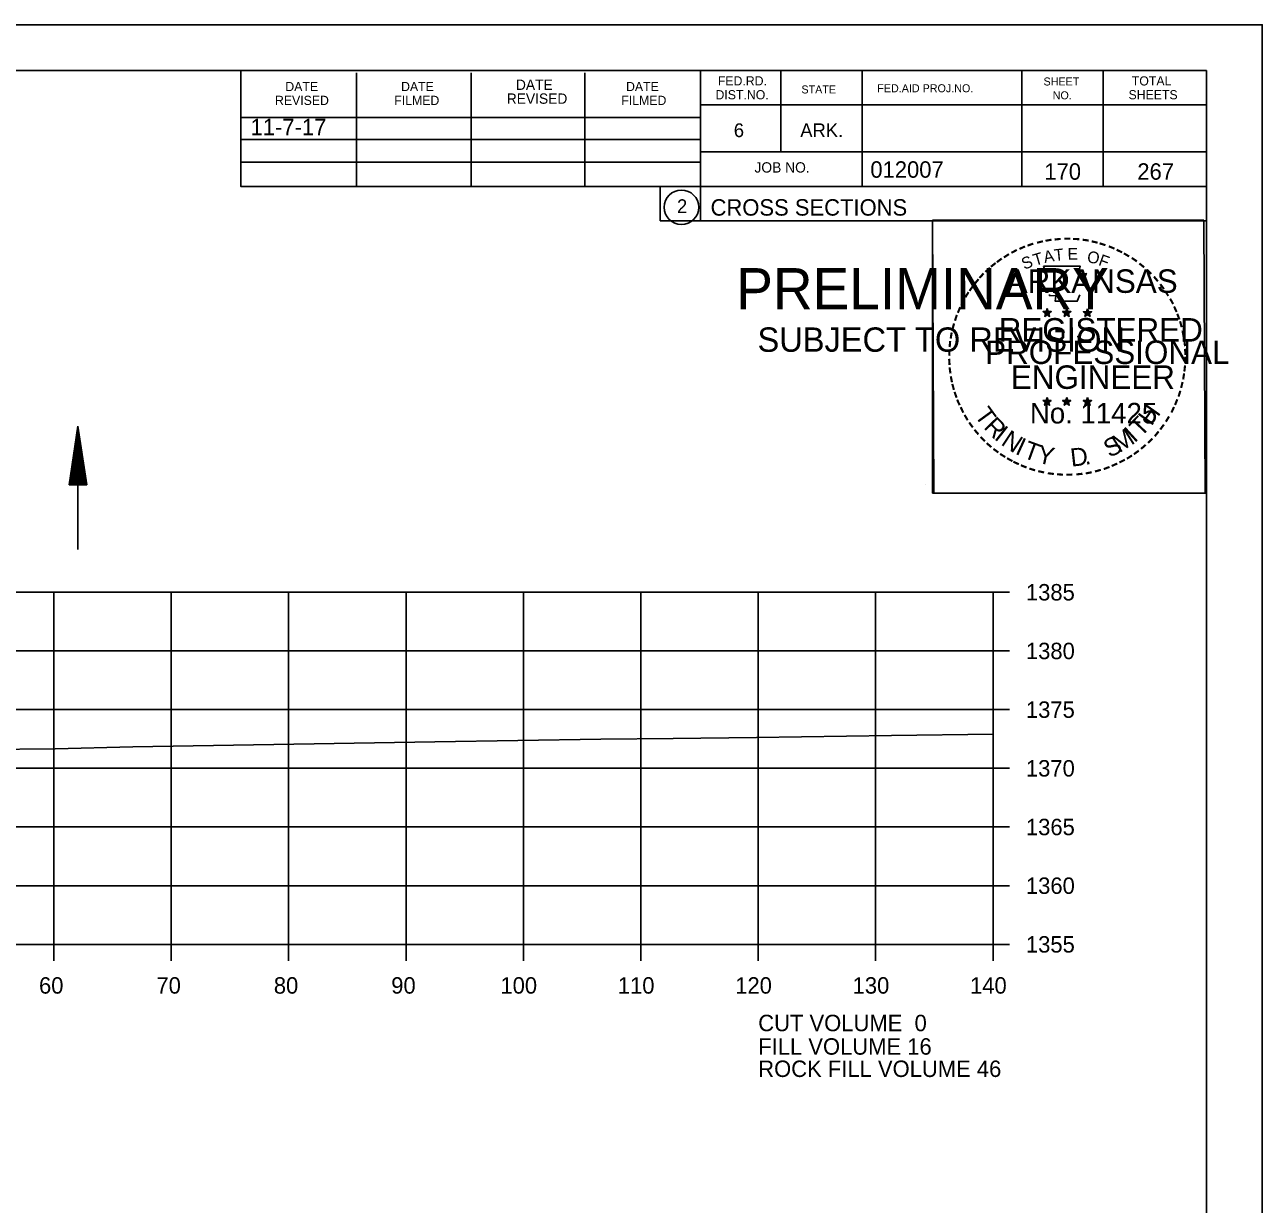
# Model space of a CAD drawing. Extents: x 1374311 to 1383814, y 384102 to 406278.
# Drawn here: x 1381686.2 to 1381791.6, y 388917.5 to 389018 of the extents above; entities that cross this region are included whole.
import ezdxf

# ---------------------------------------------------------------- set-up
doc = ezdxf.new("R2010")
doc.units = 0
for name, color, linetype in [('R_Axis', 7, 'Continuous'), ('R_Axis Annot', 7, 'Continuous'), ('R_Border', 7, 'Continuous'), ('R_Border PE', 7, 'Continuous'), ('R_Border Prem', 7, 'Continuous'), ('R_Draft', 7, 'Continuous'), ('R_Exist Surface', 7, 'Continuous'), ('R_Fin Surface', 7, 'Continuous'), ('R_Grid', 7, 'Continuous'), ('R_No Plot', 7, 'Continuous'), ('R_Water', 7, 'Continuous')]:
    doc.layers.add(name, color=color, linetype=linetype)

msp = doc.modelspace()

# ---------------------------------------------------------------- linework, layer by layer
at = {"layer": 'R_Axis'}
for p, q in [((1381768.66, 388939.68), (1381768.66, 388969.68)), ((1381770.06, 388969.68), (1381768.66, 388969.68)), ((1381770.06, 388964.68), (1381768.66, 388964.68)), ((1381770.06, 388959.68), (1381768.66, 388959.68)), ((1381770.06, 388954.68), (1381768.66, 388954.68)), ((1381770.06, 388949.68), (1381768.66, 388949.68)), ((1381770.06, 388944.68), (1381768.66, 388944.68)), ((1381488.66, 388939.68), (1381768.66, 388939.68)), ((1381688.66, 388938.28), (1381688.66, 388939.68)), ((1381698.66, 388938.28), (1381698.66, 388939.68)), ((1381708.66, 388938.28), (1381708.66, 388939.68)), ((1381718.66, 388938.28), (1381718.66, 388939.68)), ((1381728.66, 388938.28), (1381728.66, 388939.68)), ((1381738.66, 388938.28), (1381738.66, 388939.68)), ((1381748.66, 388938.28), (1381748.66, 388939.68)), ((1381758.66, 388938.28), (1381758.66, 388939.68)), ((1381768.66, 388938.28), (1381768.66, 388939.68)), ((1381770.06, 388939.68), (1381768.66, 388939.68))]:
    msp.add_line(p, q, dxfattribs=at)
at = {"layer": 'R_Border'}
for p, q in [((1381470.66, 389014.14), (1381786.84, 389014.14)), ((1381704.58, 389004.26), (1381704.58, 389014.14)), ((1381714.44, 389004.26), (1381714.44, 389013.94)), ((1381724.2, 389004.26), (1381724.2, 389013.94)), ((1381733.88, 389004.26), (1381733.88, 389013.94)), ((1381743.74, 389014.14), (1381743.74, 389001.34)), ((1381750.58, 389014.14), (1381750.58, 389007.2)), ((1381757.52, 389014.14), (1381757.52, 389004.26)), ((1381771.1, 389014.14), (1381771.1, 389004.26)), ((1381778.04, 389014.14), (1381778.04, 389004.26)), ((1381786.84, 388808.68), (1381786.84, 389014.14)), ((1381786.84, 389011.2), (1381743.74, 389011.2)), ((1381786.84, 389011.22), (1381786.84, 389011.22)), ((1381704.58, 389010.12), (1381743.74, 389010.12)), ((1381704.58, 389008.26), (1381743.74, 389008.26)), ((1381786.84, 389007.2), (1381743.74, 389007.2)), ((1381746.7, 389007.2), (1381786.84, 389007.2)), ((1381704.58, 389004.26), (1381704.58, 389006.32)), ((1381704.58, 389006.32), (1381743.74, 389006.32)), ((1381786.84, 389004.26), (1381704.58, 389004.26)), ((1381743.74, 389001.34), (1381786.84, 389001.34))]:
    msp.add_line(p, q, dxfattribs=at)
msp.add_circle((1381742.12, 389002.48), 1.47, dxfattribs=at)
at = {"layer": 'R_Border PE'}
for p, q in [((1381773.27, 388993.85), (1381773.23, 388993.6)), ((1381773.27, 388993.48), (1381773.27, 388993.85)), ((1381773.27, 388993.85), (1381773.32, 388993.6)), ((1381774.94, 388993.85), (1381774.9, 388993.6)), ((1381774.94, 388993.48), (1381774.94, 388993.85)), ((1381774.94, 388993.85), (1381774.99, 388993.6)), ((1381776.71, 388993.84), (1381776.66, 388993.59)), ((1381776.71, 388993.47), (1381776.71, 388993.84)), ((1381776.71, 388993.84), (1381776.75, 388993.59)), ((1381772.92, 388993.6), (1381773.27, 388993.48)), ((1381772.92, 388993.6), (1381773.18, 388993.55)), ((1381772.92, 388993.6), (1381773.16, 388993.47)), ((1381773.06, 388993.19), (1381773.27, 388993.48)), ((1381773.06, 388993.19), (1381773.18, 388993.43)), ((1381773.06, 388993.19), (1381773.27, 388993.4)), ((1381773.62, 388993.6), (1381773.27, 388993.48)), ((1381773.48, 388993.19), (1381773.27, 388993.48)), ((1381773.48, 388993.19), (1381773.27, 388993.4)), ((1381773.62, 388993.6), (1381773.33, 388993.55)), ((1381773.48, 388993.19), (1381773.35, 388993.48)), ((1381773.62, 388993.6), (1381773.41, 388993.49)), ((1381774.59, 388993.6), (1381774.94, 388993.48)), ((1381774.59, 388993.6), (1381774.85, 388993.55)), ((1381774.59, 388993.6), (1381774.83, 388993.47)), ((1381774.73, 388993.19), (1381774.94, 388993.48)), ((1381774.73, 388993.19), (1381774.85, 388993.43)), ((1381774.73, 388993.19), (1381774.94, 388993.4)), ((1381775.29, 388993.6), (1381774.94, 388993.48)), ((1381775.15, 388993.19), (1381774.94, 388993.48)), ((1381775.15, 388993.19), (1381774.94, 388993.4)), ((1381775.29, 388993.6), (1381775, 388993.55)), ((1381775.15, 388993.19), (1381775.02, 388993.48)), ((1381775.29, 388993.6), (1381775.08, 388993.49)), ((1381776.36, 388993.58), (1381776.71, 388993.47)), ((1381776.36, 388993.58), (1381776.61, 388993.54)), ((1381776.36, 388993.58), (1381776.59, 388993.46)), ((1381776.49, 388993.18), (1381776.71, 388993.47)), ((1381776.49, 388993.18), (1381776.62, 388993.42)), ((1381776.49, 388993.18), (1381776.7, 388993.39)), ((1381776.92, 388993.18), (1381776.7, 388993.39)), ((1381777.05, 388993.58), (1381776.71, 388993.47)), ((1381776.92, 388993.18), (1381776.71, 388993.47)), ((1381777.05, 388993.58), (1381776.77, 388993.53)), ((1381776.92, 388993.18), (1381776.78, 388993.47)), ((1381777.05, 388993.58), (1381776.85, 388993.48)), ((1381772.92, 388986.02), (1381773.27, 388985.91)), ((1381772.92, 388986.02), (1381773.17, 388985.98)), ((1381772.92, 388986.02), (1381773.16, 388985.9)), ((1381773.05, 388985.61), (1381773.27, 388985.91)), ((1381773.05, 388985.61), (1381773.18, 388985.86)), ((1381773.05, 388985.61), (1381773.27, 388985.83)), ((1381773.27, 388986.28), (1381773.23, 388986.02)), ((1381773.27, 388985.91), (1381773.27, 388986.28)), ((1381773.27, 388986.28), (1381773.32, 388986.03)), ((1381773.61, 388986.02), (1381773.27, 388985.91)), ((1381773.48, 388985.61), (1381773.27, 388985.91)), ((1381773.48, 388985.61), (1381773.27, 388985.83)), ((1381773.61, 388986.02), (1381773.33, 388985.97)), ((1381773.48, 388985.61), (1381773.34, 388985.91)), ((1381773.61, 388986.02), (1381773.41, 388985.92)), ((1381774.59, 388986.02), (1381774.94, 388985.91)), ((1381774.59, 388986.02), (1381774.84, 388985.98)), ((1381774.59, 388986.02), (1381774.82, 388985.9)), ((1381774.72, 388985.61), (1381774.94, 388985.91)), ((1381774.72, 388985.61), (1381774.85, 388985.86)), ((1381774.72, 388985.61), (1381774.93, 388985.83)), ((1381774.94, 388986.28), (1381774.9, 388986.02)), ((1381775.15, 388985.61), (1381774.93, 388985.83)), ((1381774.94, 388985.91), (1381774.94, 388986.28)), ((1381774.94, 388986.28), (1381774.99, 388986.03)), ((1381775.28, 388986.02), (1381774.94, 388985.91)), ((1381775.15, 388985.61), (1381774.94, 388985.91)), ((1381775.28, 388986.02), (1381775, 388985.97)), ((1381775.15, 388985.61), (1381775.01, 388985.91)), ((1381775.28, 388986.02), (1381775.08, 388985.92)), ((1381776.35, 388986.01), (1381776.7, 388985.9)), ((1381776.35, 388986.01), (1381776.61, 388985.97)), ((1381776.35, 388986.01), (1381776.59, 388985.89)), ((1381776.49, 388985.6), (1381776.7, 388985.9)), ((1381776.49, 388985.6), (1381776.61, 388985.85)), ((1381776.49, 388985.6), (1381776.7, 388985.82)), ((1381776.7, 388986.27), (1381776.66, 388986.01)), ((1381776.7, 388985.9), (1381776.7, 388986.27)), ((1381776.7, 388986.27), (1381776.75, 388986.02)), ((1381777.05, 388986.01), (1381776.7, 388985.9)), ((1381776.92, 388985.6), (1381776.7, 388985.9)), ((1381776.92, 388985.6), (1381776.7, 388985.82)), ((1381777.05, 388986.01), (1381776.76, 388985.96)), ((1381776.92, 388985.6), (1381776.78, 388985.9)), ((1381777.05, 388986.01), (1381776.85, 388985.91))]:
    msp.add_line(p, q, dxfattribs=at)
for points in [[(1381772.96, 388997.47), (1381773.23, 388996.65)], [(1381776.47, 388996.55), (1381776.62, 388996.84), (1381775.93, 388996.81), (1381776.08, 388997.47), (1381772.96, 388997.47)], [(1381773.46, 388995.05), (1381773.46, 388994.96), (1381774.02, 388994.94), (1381773.96, 388994.47), (1381775.83, 388994.47), (1381776.04, 388995.01)], [(1381773.27, 388993.85), (1381773.48, 388993.19), (1381772.92, 388993.6), (1381773.62, 388993.6), (1381773.06, 388993.19), (1381773.27, 388993.85)], [(1381774.94, 388993.85), (1381775.15, 388993.19), (1381774.59, 388993.6), (1381775.29, 388993.6), (1381774.73, 388993.19), (1381774.94, 388993.85)], [(1381776.71, 388993.84), (1381776.92, 388993.18), (1381776.36, 388993.58), (1381777.05, 388993.58), (1381776.49, 388993.18), (1381776.71, 388993.84)], [(1381773.27, 388986.28), (1381773.48, 388985.61), (1381772.92, 388986.02), (1381773.61, 388986.02), (1381773.05, 388985.61), (1381773.27, 388986.28)], [(1381774.94, 388986.28), (1381775.15, 388985.61), (1381774.59, 388986.02), (1381775.28, 388986.02), (1381774.72, 388985.61), (1381774.94, 388986.28)], [(1381776.7, 388986.27), (1381776.92, 388985.6), (1381776.35, 388986.01), (1381777.05, 388986.01), (1381776.49, 388985.6), (1381776.7, 388986.27)]]:
    msp.add_lwpolyline(points, dxfattribs=at)
for centre, radius in [((1381773.27, 388993.48), 0.172), ((1381773.27, 388993.48), 0.145), ((1381773.27, 388993.48), 0.116), ((1381773.27, 388993.48), 0.0991), ((1381773.27, 388993.48), 0.0747), ((1381773.27, 388993.48), 0.0495), ((1381773.27, 388993.48), 0.0296), ((1381774.94, 388993.48), 0.172), ((1381774.94, 388993.48), 0.145), ((1381774.94, 388993.48), 0.116), ((1381774.94, 388993.48), 0.0991), ((1381774.94, 388993.48), 0.0747), ((1381774.94, 388993.48), 0.0495), ((1381774.94, 388993.48), 0.0296), ((1381776.7, 388993.47), 0.172), ((1381776.7, 388993.47), 0.145), ((1381776.7, 388993.47), 0.116), ((1381776.7, 388993.47), 0.0991), ((1381776.7, 388993.47), 0.0747), ((1381776.7, 388993.47), 0.0495), ((1381776.7, 388993.47), 0.0296), ((1381773.27, 388985.91), 0.172), ((1381773.27, 388985.91), 0.145), ((1381773.27, 388985.91), 0.116), ((1381773.27, 388985.91), 0.0991), ((1381773.27, 388985.91), 0.0747), ((1381773.27, 388985.91), 0.0495), ((1381773.27, 388985.91), 0.0296), ((1381774.94, 388985.91), 0.172), ((1381774.94, 388985.91), 0.145), ((1381774.94, 388985.91), 0.116), ((1381774.94, 388985.91), 0.0991), ((1381774.94, 388985.91), 0.0747), ((1381774.94, 388985.91), 0.0495), ((1381774.94, 388985.91), 0.0296), ((1381776.7, 388985.9), 0.172), ((1381776.7, 388985.9), 0.145), ((1381776.7, 388985.9), 0.116), ((1381776.7, 388985.9), 0.0991), ((1381776.7, 388985.9), 0.0747), ((1381776.7, 388985.9), 0.0495), ((1381776.7, 388985.9), 0.0296)]:
    msp.add_circle(centre, radius, dxfattribs=at)
at = {"layer": 'R_Draft'}
for p, q in [((1381689.97, 388978.83), (1381690.72, 388983.83)), ((1381691.47, 388978.83), (1381690.72, 388983.83)), ((1381690.09, 388978.83), (1381690.72, 388983)), ((1381690.22, 388978.83), (1381690.72, 388982.14)), ((1381691.34, 388978.83), (1381690.72, 388983)), ((1381691.22, 388978.83), (1381690.72, 388982.14)), ((1381690.35, 388978.83), (1381690.72, 388981.31)), ((1381691.09, 388978.83), (1381690.72, 388981.31)), ((1381690.47, 388978.83), (1381690.72, 388980.46)), ((1381690.96, 388978.83), (1381690.72, 388980.46)), ((1381690.6, 388978.83), (1381690.72, 388979.62)), ((1381690.84, 388978.83), (1381690.72, 388979.62)), ((1381691.47, 388978.83), (1381689.97, 388978.83))]:
    msp.add_line(p, q, dxfattribs=at)
at = {"layer": 'R_Exist Surface'}
msp.add_lwpolyline([(1381567.33, 388953.99), (1381575.78, 388954.3), (1381586.09, 388955.07), (1381589.93, 388955.49), (1381596.86, 388955.76), (1381599.54, 388955.9), (1381601.13, 388955.76), (1381605.73, 388955.36), (1381615.89, 388955.54), (1381623.65, 388955.68), (1381646.48, 388956.09), (1381652.87, 388956.11), (1381674.54, 388956.12), (1381675.72, 388956.14), (1381682.71, 388956.27), (1381688.77, 388956.34), (1381695.4, 388956.5), (1381721.11, 388956.94), (1381735.25, 388957.15), (1381741.41, 388957.23), (1381748.5, 388957.31), (1381760.01, 388957.48), (1381768.66, 388957.59)], dxfattribs=at)
at = {"layer": 'R_Grid'}
for p, q in [((1381488.66, 388969.68), (1381768.66, 388969.68)), ((1381688.66, 388939.68), (1381688.66, 388969.68)), ((1381698.66, 388939.68), (1381698.66, 388969.68)), ((1381708.66, 388939.68), (1381708.66, 388969.68)), ((1381718.66, 388939.68), (1381718.66, 388969.68)), ((1381728.66, 388939.68), (1381728.66, 388969.68)), ((1381738.66, 388939.68), (1381738.66, 388969.68)), ((1381748.66, 388939.68), (1381748.66, 388969.68)), ((1381758.66, 388939.68), (1381758.66, 388969.68)), ((1381768.66, 388939.68), (1381768.66, 388969.68)), ((1381488.66, 388964.68), (1381768.66, 388964.68)), ((1381488.66, 388959.68), (1381768.66, 388959.68)), ((1381488.66, 388954.68), (1381768.66, 388954.68)), ((1381488.66, 388949.68), (1381768.66, 388949.68)), ((1381488.66, 388944.68), (1381768.66, 388944.68)), ((1381488.66, 388939.68), (1381768.66, 388939.68))]:
    msp.add_line(p, q, dxfattribs=at)
at = {"layer": 'R_No Plot'}
for p, q in [((1381458.26, 389018.04), (1381791.59, 389018.04)), ((1381762.87, 388978.88), (1381762.87, 388978.88))]:
    msp.add_line(p, q, dxfattribs=at)
for points in [[(1381458.25, 389018.04), (1381791.59, 389018.04), (1381791.59, 388804.7), (1381458.25, 388804.7)], [(1381704.58, 389014.14), (1381704.58, 389004.26), (1381740.31, 389004.26), (1381740.31, 389001.34), (1381763.51, 389001.34), (1381763.51, 388978.13), (1381786.84, 388978.13), (1381786.84, 388808.68), (1381470.66, 388808.68), (1381470.66, 389014.14)], [(1381763.51, 389001.37), (1381786.61, 389001.37), (1381786.72, 388978.13), (1381763.62, 388978.13)]]:
    msp.add_lwpolyline(points, close=True, dxfattribs=at)
at = {"layer": 'R_Water'}
msp.add_line((1381690.72, 388973.33), (1381690.72, 388983.83), dxfattribs=at)

# ---------------------------------------------------------------- texts
at = {"layer": 'R_Axis Annot'}
for s, p in [('1385', (1381771.46, 388968.98)), ('1380', (1381771.46, 388963.98)), ('1375', (1381771.46, 388958.98)), ('1370', (1381771.46, 388953.98)), ('1365', (1381771.46, 388948.98)), ('1360', (1381771.46, 388943.98)), ('1355', (1381771.46, 388938.98)), ('60', (1381687.4, 388935.48)), ('70', (1381697.4, 388935.48)), ('80', (1381707.4, 388935.48)), ('90', (1381717.4, 388935.48)), ('100', (1381726.7, 388935.48)), ('110', (1381736.7, 388935.48)), ('120', (1381746.7, 388935.48)), ('130', (1381756.7, 388935.48)), ('140', (1381766.7, 388935.48)), ('CUT VOLUME  0', (1381748.66, 388932.28)), ('FILL VOLUME 16', (1381748.66, 388930.28)), ('ROCK FILL VOLUME 46', (1381748.66, 388928.38))]:
    msp.add_text(s, height=1.4, dxfattribs=at).set_placement(p)
at = {"layer": 'R_Border'}
for s, height, p in [('DATE', 0.782, (1381708.38, 389012.38)), ('DATE', 0.782, (1381718.24, 389012.38)), ('DATE', 0.879, (1381728.02, 389012.48)), ('DATE', 0.782, (1381737.4, 389012.38)), ('FED.RD.', 0.782, (1381745.22, 389012.86)), ('STATE', 0.684, (1381752.34, 389012.18)), ('FED.AID PROJ.NO.', 0.684, (1381758.8, 389012.28)), ('SHEET', 0.684, (1381772.96, 389012.86)), ('TOTAL', 0.782, (1381780.48, 389012.86)), ('REVISED', 0.782, (1381707.5, 389011.2)), ('FILMED', 0.782, (1381717.66, 389011.2)), ('REVISED', 0.879, (1381727.24, 389011.3)), ('FILMED', 0.782, (1381737, 389011.2)), ('DIST.NO.', 0.782, (1381745.02, 389011.68)), ('NO.', 0.684, (1381773.74, 389011.68)), ('SHEETS', 0.782, (1381780.2, 389011.68)), ('6', 1.17, (1381746.58, 389008.46)), ('ARK.', 1.172, (1381752.24, 389008.46)), ('012007', 1.4, (1381758.21, 389005)), ('JOB NO.', 0.879, (1381748.34, 389005.44)), ('2', 1.17, (1381741.74, 389001.99)), ('CROSS SECTIONS', 1.4, (1381744.6, 389001.77))]:
    msp.add_text(s, height=height, rotation=360, dxfattribs=at).set_placement(p)
at = {"layer": 'R_Border PE'}
for s, height, rotation, p in [('-', 1.6, 24.3072, (1381771.08, 388998.33)), ('-', 1.6, 19.1761, (1381771.71, 388998.6)), ('-', 1.6, 13.6301, (1381772.46, 388998.84)), ('-', 1.6, 10.2193, (1381773.14, 388999)), ('-', 1.6, 5.8968, (1381773.87, 388999.11)), ('-', 1.6, 0.1862, (1381774.64, 388999.19)), ('E', 1, 0.8323, (1381775.01, 388998.01)), ('-', 1.6, 357.743, (1381775.36, 388999.17)), ('-', 1.6, 352.1617, (1381776.11, 388999.12)), ('-', 1.6, 347.2049, (1381776.83, 388999)), ('-', 1.6, 342.3362, (1381777.46, 388998.85)), ('-', 1.6, 337.8551, (1381778.2, 388998.62)), ('-', 1.6, 36.2317, (1381769.27, 388997.25)), ('-', 1.6, 34.0636, (1381769.85, 388997.64)), ('-', 1.6, 28.7918, (1381770.44, 388998.01)), ('S', 1, 21.594, (1381771.32, 388997.15)), ('T', 1, 16.4036, (1381772.23, 388997.48)), ('A', 1, 11.2132, (1381773.06, 388997.73)), ('T', 1, 6.0228, (1381773.91, 388997.9)), ('O', 1, 350.4515, (1381776.62, 388997.8)), ('F', 1, 340.0707, (1381777.57, 388997.57)), ('-', 1.6, 334.1211, (1381778.83, 388998.35)), ('-', 1.6, 329.6409, (1381779.41, 388998.07)), ('-', 1.6, 325.8627, (1381780.05, 388997.71)), ('-', 1.6, 48.423, (1381767.91, 388995.98)), ('-', 1.6, 42.9622, (1381768.36, 388996.45)), ('-', 1.6, 38.9507, (1381768.79, 388996.87)), ('ARKANSAS', 2, 360, (1381769.82, 388995.19)), ('-', 1.6, 320.5297, (1381780.66, 388997.28)), ('-', 1.6, 315.5786, (1381781.26, 388996.8)), ('-', 1.6, 54.2325, (1381767.1, 388994.92)), ('-', 1.6, 50.6142, (1381767.51, 388995.49)), ('-', 1.6, 309.8797, (1381781.83, 388996.25)), ('-', 1.6, 306.6522, (1381782.35, 388995.64)), ('-', 1.6, 58.0706, (1381766.77, 388994.4)), ('-', 1.4, 303.6753, (1381782.84, 388995.08)), ('-', 1.6, 67.7743, (1381766.2, 388993.17)), ('-', 1.6, 62.8713, (1381766.46, 388993.78)), ('-', 1.6, 299.6684, (1381783.16, 388994.47)), ('-', 1.6, 294.6628, (1381783.48, 388993.86)), ('-', 1.6, 72.3945, (1381765.98, 388992.54)), ('REGISTERED', 2, 360, (1381769.14, 388991.04)), ('DWB', 0.01, 360, (1381773.26, 388993.48)), ('DWB', 0.01, 360, (1381774.93, 388993.48)), ('DWB', 0.01, 360, (1381776.69, 388993.47)), ('-', 1.6, 290.5728, (1381783.74, 388993.28)), ('-', 1.6, 285.1233, (1381783.97, 388992.7)), ('-', 1.6, 81.2013, (1381765.65, 388991.11)), ('-', 1.6, 75.461, (1381765.78, 388991.83)), ('-', 1.6, 280.5493, (1381784.17, 388991.96)), ('-', 1.6, 85.1863, (1381765.57, 388990.42)), ('PROFESSIONAL', 2, 360, (1381767.99, 388989.13)), ('-', 1.6, 276.5962, (1381784.33, 388991.19)), ('-', 1.6, 94.1959, (1381765.58, 388989)), ('-', 1.6, 89.0622, (1381765.55, 388989.72)), ('-', 1.6, 274.3301, (1381784.39, 388990.47)), ('-', 1.6, 269.9407, (1381784.43, 388989.84)), ('-', 1.6, 98.9479, (1381765.66, 388988.33)), ('ENGINEER', 2, 360, (1381770.18, 388987.01)), ('-', 1.6, 263.5172, (1381784.41, 388989.17)), ('-', 1.6, 101.7149, (1381765.79, 388987.6)), ('-', 1.6, 105.4578, (1381765.95, 388987)), ('-', 1.6, 255.7626, (1381784.23, 388987.84)), ('-', 1.6, 260.9953, (1381784.34, 388988.52)), ('-', 1.6, 109.0874, (1381766.17, 388986.37)), ('-', 1.6, 252.8681, (1381784.05, 388987.12)), ('-', 1.6, 114.0643, (1381766.42, 388985.78)), ('-', 1.6, 115.7289, (1381766.73, 388985.16)), ('T', 1.54, 306.0406, (1381767.03, 388984.75)), ('No. 11425', 1.757, 360, (1381771.8, 388984.06)), ('DWB', 0.01, 360, (1381773.25, 388985.91)), ('DWB', 0.01, 360, (1381774.92, 388985.91)), ('DWB', 0.01, 360, (1381776.69, 388985.9)), ('H', 1.54, 54.6088, (1381782.15, 388983.78)), ('-', 1.6, 244.6197, (1381783.56, 388985.82)), ('-', 1.6, 247.8887, (1381783.82, 388986.44)), ('-', 1.6, 120.4471, (1381767.08, 388984.57)), ('R', 1.54, 314.005, (1381767.79, 388983.7)), ('T', 1.54, 46.6444, (1381781.26, 388982.84)), ('-', 1.6, 239.0712, (1381783.17, 388985.06)), ('-', 1.6, 125.8934, (1381767.49, 388984.01)), ('-', 1.6, 130.7181, (1381767.95, 388983.46)), ('I', 1.54, 321.9694, (1381768.69, 388982.77)), ('N', 1.54, 326.5002, (1381769.26, 388982.3)), ('M', 1.54, 32.6563, (1381779.41, 388981.52)), ('I', 1.54, 42.1136, (1381780.7, 388982.36)), ('-', 1.6, 231.2538, (1381782.34, 388983.84)), ('-', 1.6, 233.8452, (1381782.77, 388984.41)), ('-', 1.6, 134.2238, (1381768.47, 388982.91)), ('-', 1.6, 138.9338, (1381768.99, 388982.45)), ('I', 1.54, 335.3603, (1381770.47, 388981.51)), ('T', 1.54, 339.8912, (1381771.13, 388981.18)), ('Y', 1.54, 347.8556, (1381772.34, 388980.74)), ('S', 1.54, 26.9312, (1381778.57, 388981.11)), ('-', 1.6, 221.0851, (1381781.33, 388982.77)), ('-', 1.6, 225.7653, (1381781.86, 388983.28)), ('-', 1.6, 144.6463, (1381769.55, 388982.04)), ('-', 1.6, 148.0898, (1381770.11, 388981.67)), ('-', 1.6, 151.5704, (1381770.69, 388981.35)), ('D', 1.54, 6.3969, (1381775.33, 388980.38)), ('-', 1.6, 212.2491, (1381780.25, 388981.91)), ('-', 1.6, 215.7363, (1381780.79, 388982.3)), ('-', 1.6, 154.6002, (1381771.21, 388981.1)), ('-', 1.6, 158.5612, (1381771.83, 388980.85)), ('-', 1.6, 162.7983, (1381772.52, 388980.63)), ('-', 1.6, 167.5555, (1381773.24, 388980.47)), ('.', 1.54, 13.7642, (1381776.52, 388980.51)), ('-', 1.6, 195.4743, (1381777.77, 388980.73)), ('-', 1.6, 200.7184, (1381778.45, 388980.97)), ('-', 1.6, 204.2516, (1381779.07, 388981.25)), ('-', 1.6, 207.3568, (1381779.69, 388981.57)), ('-', 1.6, 173.1155, (1381774.01, 388980.36)), ('-', 1.6, 176.5183, (1381774.76, 388980.31)), ('-', 1.6, 181.5918, (1381775.5, 388980.33)), ('-', 1.6, 185.8167, (1381776.31, 388980.4)), ('-', 1.6, 191.2858, (1381777.04, 388980.53))]:
    msp.add_text(s, height=height, rotation=rotation, dxfattribs=at).set_placement(p)
at = {"layer": 'R_Border Prem'}
for s, height, p in [('PRELIMINARY', 3.5, (1381746.79, 388993.8)), ('DWB', 0.01, (1381747.53, 388995.65)), ('SUBJECT TO REVISION', 2.0751, (1381748.6, 388990.17))]:
    msp.add_text(s, height=height, rotation=360, dxfattribs=at).set_placement(p)
at = {"layer": 'R_Fin Surface'}
msp.add_text('11-7-17', height=1.4, dxfattribs=at).set_placement((1381705.42, 389008.62))
at = {"layer": 'R_Water'}
for s, p in [('170', (1381773.03, 389004.83)), ('267', (1381780.95, 389004.83))]:
    msp.add_text(s, height=1.4, rotation=360, dxfattribs=at).set_placement(p)

doc.saveas('drawing.dxf')
